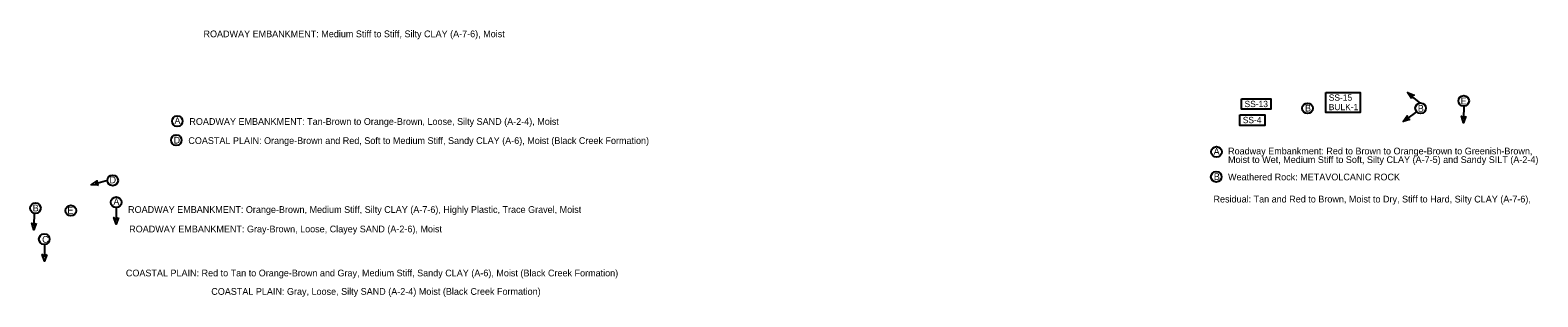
# Model space of a CAD drawing. Extents: x -1079 to 303, y -11 to 4017.
# Drawn here: x -1079 to -743.8, y 367.3 to 426.6 of the extents above; entities that cross this region are included whole.
import ezdxf

# ---------------------------------------------------------------- set-up
doc = ezdxf.new("R2010")
doc.units = 0
for name, color, linetype in [('Misc Plan Tools Cell', 7, 'Continuous'), ('Prop Road Sect_ Boring - Header (Sample Box + Tx)', 7, 'Continuous'), ('Prop Road Sect_ Material - Bubble + Leader + Bubble Tx', 7, 'Continuous'), ('Prop Road Sect_ Material - Tx (Composite Desc)', 7, 'Continuous')]:
    doc.layers.add(name, color=color, linetype=linetype)

msp = doc.modelspace()

# ---------------------------------------------------------------- linework, layer by layer
at = {"layer": 'Misc Plan Tools Cell'}
for points in [[(-771.91, 411.36), (-772.77, 412.69), (-771.29, 412.14), (-771.99, 412.06)], [(-772.23, 406.74), (-773.74, 406.26), (-772.82, 407.55), (-772.93, 406.85)], [(-759.77, 407.46), (-760.29, 405.96), (-760.77, 407.47), (-760.28, 406.96)], [(-1063.85, 392.07), (-1065.43, 392.14), (-1064.12, 393.03), (-1064.46, 392.41)], [(-1077.67, 383.64), (-1078.19, 382.15), (-1078.67, 383.65), (-1078.18, 383.15)], [(-1059.41, 384.9), (-1059.93, 383.41), (-1060.41, 384.91), (-1059.91, 384.41)], [(-1075.36, 376.69), (-1075.88, 375.2), (-1076.36, 376.7), (-1075.86, 376.2)]]:
    msp.add_lwpolyline(points, close=True, dxfattribs=at)
at = {"layer": 'Prop Road Sect_ Boring - Header (Sample Box + Tx)'}
for points in [[(-790.95, 412.7), (-783.28, 412.7), (-783.28, 408.25), (-790.95, 408.25)], [(-809.68, 411.28), (-803.12, 411.28), (-803.12, 408.98), (-809.68, 408.98)], [(-810.08, 407.71), (-804.47, 407.71), (-804.47, 405.4), (-810.08, 405.4)]]:
    msp.add_lwpolyline(points, close=True, dxfattribs=at)
at = {"layer": 'Prop Road Sect_ Material - Bubble + Leader + Bubble Tx'}
for p, q in [((-769.88, 410.37), (-771.99, 412.06)), ((-760.24, 409.67), (-760.28, 406.96)), ((-770.74, 408.44), (-772.93, 406.85)), ((-1061.86, 393.15), (-1064.46, 392.41)), ((-1078.14, 385.85), (-1078.18, 383.15)), ((-1059.88, 387.11), (-1059.91, 384.41)), ((-1075.83, 378.9), (-1075.86, 376.2))]:
    msp.add_line(p, q, dxfattribs=at)
for centre in [(-795.01, 409.19), (-769.85, 409.21), (-760.27, 410.84), (-1046.31, 406.34), (-1046.53, 402.1), (-815.23, 399.5), (-1060.68, 393.16), (-815.28, 393.97), (-1059.91, 388.29), (-1077.86, 386.99), (-1070, 386.44), (-1075.89, 380.08)]:
    msp.add_circle(centre, 1.18, dxfattribs=at)

# ---------------------------------------------------------------- texts
at = {"layer": 'Prop Road Sect_ Boring - Header (Sample Box + Tx)'}
for s, p in [('SS-13', (-809, 409.46)), ('SS-15', (-790.27, 410.88)), ('BULK-1', (-790.27, 408.78)), ('SS-4', (-809.4, 405.89))]:
    msp.add_text(s, height=1.4, dxfattribs=at).set_placement(p)
at = {"layer": 'Prop Road Sect_ Material - Tx (Composite Desc)'}
for s, p in [('ROADWAY EMBANKMENT: Medium Stiff to Stiff, Silty CLAY (A-7-6), Moist', (-1040.49, 425)), ('B', (-795.56, 408.48)), ('B', (-770.46, 408.42)), ('E', (-760.95, 410.05)), ('A', (-1046.95, 405.68)), ('ROADWAY EMBANKMENT: Tan-Brown to Orange-Brown, Loose, Silty SAND (A-2-4), Moist', (-1043.63, 405.51)), ('D', (-1047.14, 401.36)), ('COASTAL PLAIN: Orange-Brown and Red, Soft to Medium Stiff, Sandy CLAY (A-6), Moist (Black Creek Formation)', (-1043.86, 401.26)), ('A', (-815.88, 398.85)), ('Roadway Embankment: Red to Brown to Orange-Brown to Greenish-Brown, ', (-812.66, 398.94)), ('Moist to Wet, Medium Stiff to Soft, Silty CLAY (A-7-5) and Sandy SILT (A-2-4)', (-812.66, 397.03)), ('D', (-1061.38, 392.52)), ('B', (-815.83, 393.26)), ('Weathered Rock: METAVOLCANIC ROCK', (-812.67, 393.17)), ('A', (-1060.53, 387.66)), ('Residual: Tan and Red to Brown, Moist to Dry, Stiff to Hard, Silty CLAY (A-7-6), ', (-815.9, 388.25)), ('B', (-1078.48, 386.26)), ('E', (-1070.76, 385.77)), ('ROADWAY EMBANKMENT: Orange-Brown, Medium Stiff, Silty CLAY (A-7-6), Highly Plastic, Trace Gravel, Moist', (-1057.26, 385.93)), ('ROADWAY EMBANKMENT: Gray-Brown, Loose, Clayey SAND (A-2-6), Moist', (-1057.01, 381.6)), ('C', (-1076.37, 379.29)), ('COASTAL PLAIN: Red to Tan to Orange-Brown and Gray, Medium Stiff, Sandy CLAY (A-6), Moist (Black Creek Formation)', (-1057.75, 371.81)), ('COASTAL PLAIN: Gray, Loose, Silty SAND (A-2-4) Moist (Black Creek Formation)', (-1038.76, 367.71))]:
    msp.add_text(s, height=1.5, dxfattribs=at).set_placement(p)

doc.saveas('drawing.dxf')
